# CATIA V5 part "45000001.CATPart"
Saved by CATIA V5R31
Part number: 45000001
Revision: 2
Nomenclature: NUT_WELD
Source: Unknown
Property "部品番号(A社)": "45000001"
Property "部品名称(A社)": "NUT_WELD"
Property "Version(A社)": "2"
Property "材質": "S12C"
Property "板厚": "N/A"
Bounding box of the stored display mesh (mm): x -5.5 to 5.5, y -5.5 to 5.5, z -1 to 4.5
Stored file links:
  \\cad-nas02\CATIA1212\BODY_DEPARTMENT8\JAMA\変換データ\STEP3_最終_20240115\01_いすゞ板金\new_ファイル名修正後\CATIA_V5_20240122\45000001.CATPart
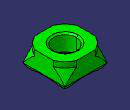
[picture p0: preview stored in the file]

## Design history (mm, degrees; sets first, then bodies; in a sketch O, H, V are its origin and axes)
Body1 "MANIFOLD_SOLID_BREP #325" (main body)
  Solid1: solid without history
